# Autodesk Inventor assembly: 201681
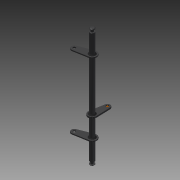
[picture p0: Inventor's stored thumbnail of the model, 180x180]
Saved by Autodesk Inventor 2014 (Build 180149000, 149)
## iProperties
Created: 2007-10
Part Number: 201681
Document SubType Name: Weldment
Designer: TH
Weld Material: Welded Steel Mild (Black-Flat)
Mass: 742.807 g
Surface Area: 353.059 cm^2
Volume: 94.6232 cm^3
Density: 7.85016 g/cm^3
Description: PIVOT LINK WELDMENT
Component Category: Lower Component
Author: TH
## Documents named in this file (4)
- C:\Users\iTools\Desktop\tutorial files\Automotive\2000\201681.iam
- C:\Users\iTools\Desktop\tutorial files\Automotive\2000\201160.ipt
- C:\Users\iTools\Desktop\tutorial files\Automotive\2000\201456.ipt
- C:\Users\iTools\Desktop\tutorial files\Automotive\2000\201086.ipt
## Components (4 placed, 3 different names)
1. 201160:1 — Flush:2, Flush:3, Angle:1
2. 201160:2 — Flush:1, Flush:3
3. 201456:1 — Flush:1, Flush:2, Mate:3, Mate:4
4. 201086:1 — Mate:3, Angle:1, Mate:4
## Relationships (6: Flush 3, Mate 2, Angle 1)
- Flush:1: 201160:2 ↔ 201456:1
- Flush:2: 201160:1 ↔ 201456:1
- Flush:3: 201160:1 ↔ 201160:2
- Mate:3: 201456:1 ↔ 201086:1
- Angle:1: 201160:1 ↔ 201086:1
- Mate:4: 201456:1 ↔ 201086:1
